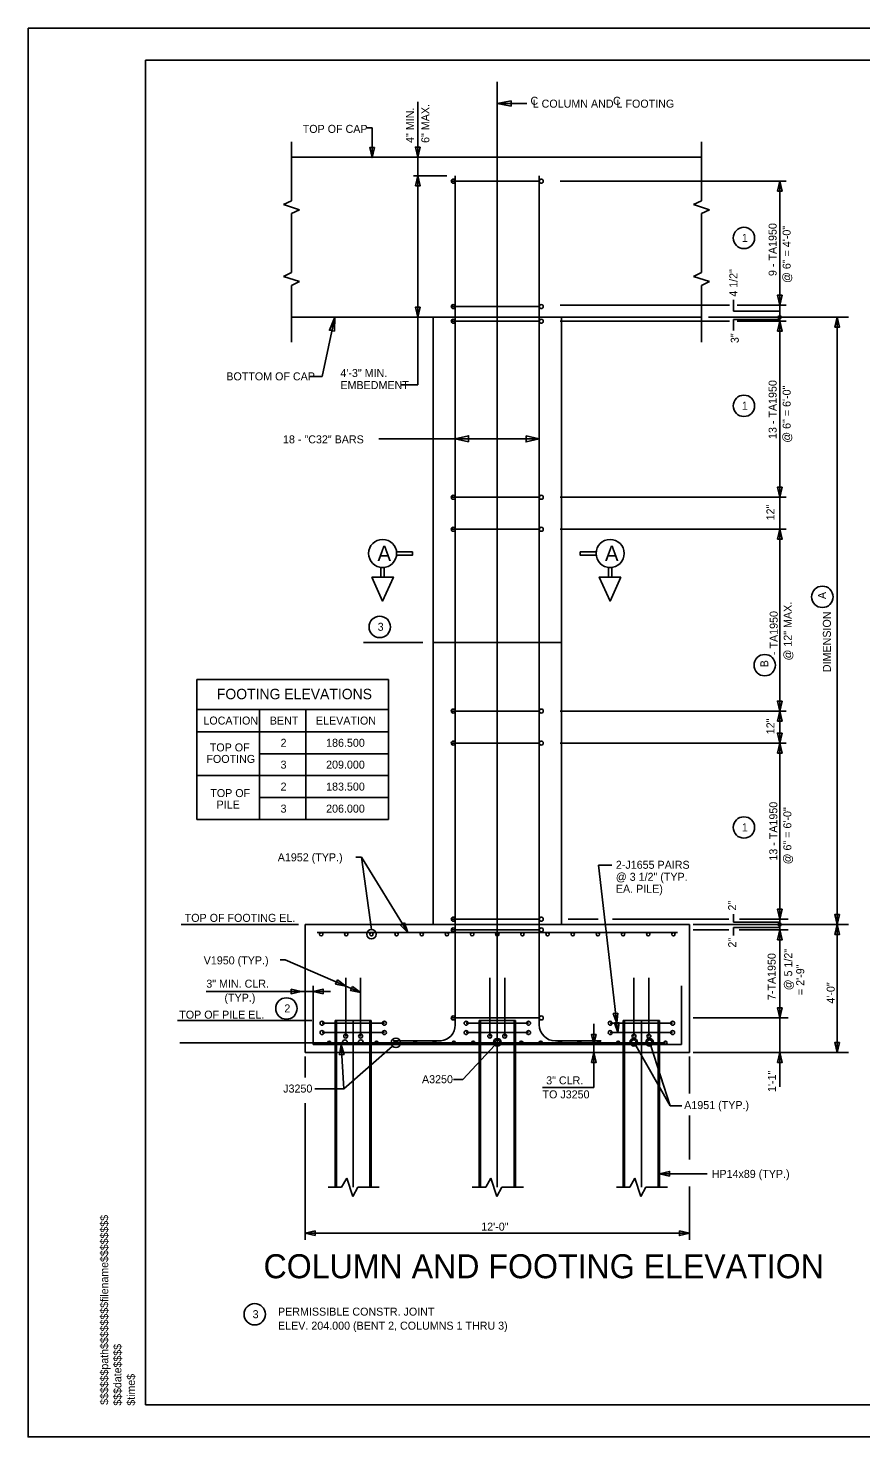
# Model space of a CAD drawing. Extents: x 1970675.2 to 1970711.3, y 796145.2 to 796167.2.
# Drawn here: x 1970675.24 to 1970688.24, y 796145.25 to 796167.25 of the extents above; entities that cross this region are included whole.
import ezdxf

# ---------------------------------------------------------------- set-up
doc = ezdxf.new("R2010")
doc.units = 0
for name, color, linetype in [('BR_AUTO DIMENSION', 7, 'Continuous'), ('BR_BORDER LINES', 7, 'Continuous'), ('BR_CENTER LINES', 7, 'Continuous'), ('BR_CONCRETE', 7, 'Continuous'), ('BR_REBAR', 7, 'Continuous'), ('BR_STRUCTURAL STEEL', 7, 'Continuous'), ('BR_TABLE LINES', 7, 'Continuous'), ('BR_TEXT', 7, 'Continuous'), ('Default', 7, 'Continuous'), ('Level 31', 7, 'Continuous'), ('RD_SHT_ID', 7, 'Continuous')]:
    doc.layers.add(name, color=color, linetype=linetype)

msp = doc.modelspace()

# ---------------------------------------------------------------- linework, layer by layer
at = {"layer": 'BR_AUTO DIMENSION'}
for p, q in [((1970681.318, 796164.939), (1970681.318, 796166.096)), ((1970682.561, 796166.069), (1970683.022, 796166.069)), ((1970681.774, 796164.939), (1970681.254, 796164.939)), ((1970681.318, 796164.939), (1970681.318, 796161.677)), ((1970683.541, 796164.857), (1970687.071, 796164.857)), ((1970686.97, 796164.857), (1970686.97, 796153.247)), ((1970686.247, 796162.829), (1970686.247, 796163.002)), ((1970686.97, 796162.92), (1970686.97, 796163.012)), ((1970683.541, 796162.92), (1970686.186, 796162.92)), ((1970686.247, 796162.829), (1970686.97, 796162.829)), ((1970686.305, 796162.92), (1970687.071, 796162.92)), ((1970679.827, 796161.807), (1970680.025, 796162.732)), ((1970683.541, 796162.67), (1970686.186, 796162.67)), ((1970685.859, 796162.732), (1970688.046, 796162.732)), ((1970686.247, 796162.696), (1970686.97, 796162.696)), ((1970686.247, 796162.696), (1970686.247, 796162.523)), ((1970686.305, 796162.67), (1970687.071, 796162.67)), ((1970686.97, 796162.67), (1970686.97, 796162.543)), ((1970687.866, 796162.732), (1970687.866, 796153.247)), ((1970679.64, 796161.807), (1970679.827, 796161.807)), ((1970681.318, 796161.677), (1970681.058, 796161.677)), ((1970680.712, 796160.832), (1970683.217, 796160.832)), ((1970683.541, 796159.92), (1970687.071, 796159.92)), ((1970683.541, 796159.42), (1970687.071, 796159.42)), ((1970680.47, 796157.65), (1970681.4, 796157.65)), ((1970683.541, 796156.581), (1970687.071, 796156.581)), ((1970683.541, 796156.081), (1970687.071, 796156.081)), ((1970680.352, 796154.299), (1970680.438, 796154.299)), ((1970680.438, 796154.299), (1970680.596, 796153.17)), ((1970680.438, 796154.299), (1970681.164, 796153.122)), ((1970684.14, 796154.176), (1970684.347, 796154.176)), ((1970684.14, 796154.176), (1970684.443, 796151.56)), ((1970683.669, 796153.331), (1970684.134, 796153.331)), ((1970684.357, 796153.331), (1970686.175, 796153.331)), ((1970686.247, 796153.41), (1970686.247, 796153.285)), ((1970686.247, 796153.285), (1970686.97, 796153.285)), ((1970686.34, 796153.331), (1970687.103, 796153.331)), ((1970679.456, 796153.247), (1970677.627, 796153.247)), ((1970685.621, 796153.247), (1970688.046, 796153.247)), ((1970685.621, 796153.164), (1970686.175, 796153.164)), ((1970686.247, 796153.074), (1970686.247, 796153.199)), ((1970686.247, 796153.199), (1970686.97, 796153.199)), ((1970686.335, 796153.164), (1970687.103, 796153.164)), ((1970686.97, 796153.247), (1970686.97, 796150.712)), ((1970687.866, 796153.247), (1970687.866, 796151.247)), ((1970679.25, 796152.695), (1970679.17, 796152.695)), ((1970679.25, 796152.695), (1970680.427, 796152.187)), ((1970679.959, 796152.203), (1970678.013, 796152.203)), ((1970679.666, 796151.747), (1970677.569, 796151.747)), ((1970685.621, 796151.789), (1970687.103, 796151.789)), ((1970686.97, 796151.747), (1970686.97, 796151.631)), ((1970684.066, 796151.695), (1970684.066, 796150.702)), ((1970680.123, 796151.372), (1970680.165, 796150.683)), ((1970680.922, 796151.35), (1970680.165, 796150.683)), ((1970682.024, 796150.825), (1970682.52, 796151.365)), ((1970685.258, 796150.414), (1970684.722, 796151.357)), ((1970685.258, 796150.414), (1970684.957, 796151.352)), ((1970679.561, 796151.187), (1970679.561, 796150.856)), ((1970685.561, 796151.187), (1970685.561, 796150.609)), ((1970685.621, 796151.247), (1970688.046, 796151.247)), ((1970680.165, 796150.683), (1970679.711, 796150.683)), ((1970681.879, 796150.825), (1970682.024, 796150.825)), ((1970683.265, 796150.702), (1970684.066, 796150.702)), ((1970679.561, 796150.458), (1970679.561, 796150.274)), ((1970679.561, 796150.274), (1970679.561, 796148.324)), ((1970685.441, 796150.414), (1970685.258, 796150.414)), ((1970685.561, 796150.263), (1970685.561, 796149.575)), ((1970685.094, 796149.355), (1970685.837, 796149.355)), ((1970679.92, 796149.144), (1970680.13, 796149.144)), ((1970680.209, 796149.288), (1970680.13, 796149.144)), ((1970680.209, 796149.288), (1970680.304, 796149)), ((1970680.382, 796149.144), (1970680.304, 796149)), ((1970680.382, 796149.144), (1970680.718, 796149.144)), ((1970682.17, 796149.144), (1970682.38, 796149.144)), ((1970682.459, 796149.288), (1970682.38, 796149.144)), ((1970682.459, 796149.288), (1970682.554, 796149)), ((1970682.632, 796149.144), (1970682.554, 796149)), ((1970682.632, 796149.144), (1970682.968, 796149.144)), ((1970684.42, 796149.144), (1970684.63, 796149.144)), ((1970684.709, 796149.288), (1970684.63, 796149.144)), ((1970684.709, 796149.288), (1970684.804, 796149)), ((1970684.882, 796149.144), (1970684.804, 796149)), ((1970684.882, 796149.144), (1970685.218, 796149.144)), ((1970685.561, 796149.158), (1970685.561, 796148.324)), ((1970679.561, 796148.426), (1970685.561, 796148.426))]:
    msp.add_line(p, q, dxfattribs=at)
for points in [[(1970682.777, 796166.028), (1970682.561, 796166.069), (1970682.777, 796166.111)], [(1970681.354, 796165.388), (1970681.318, 796165.232), (1970681.282, 796165.388)], [(1970680.641, 796165.381), (1970680.605, 796165.225), (1970680.569, 796165.381)], [(1970681.282, 796164.783), (1970681.318, 796164.939), (1970681.354, 796164.783)], [(1970686.934, 796164.701), (1970686.97, 796164.857), (1970687.006, 796164.701)], [(1970687.006, 796163.076), (1970686.97, 796162.92), (1970686.934, 796163.076)], [(1970681.354, 796162.888), (1970681.318, 796162.732), (1970681.282, 796162.888)], [(1970680.02, 796162.512), (1970680.025, 796162.732), (1970679.939, 796162.529)], [(1970686.934, 796162.514), (1970686.97, 796162.67), (1970687.006, 796162.514)], [(1970687.83, 796162.576), (1970687.866, 796162.732), (1970687.902, 796162.576)], [(1970682.112, 796160.784), (1970681.904, 796160.832), (1970682.112, 796160.88)], [(1970683.009, 796160.88), (1970683.217, 796160.832), (1970683.009, 796160.784)], [(1970687.006, 796160.076), (1970686.97, 796159.92), (1970686.934, 796160.076)], [(1970686.934, 796159.264), (1970686.97, 796159.42), (1970687.006, 796159.264)], [(1970687.006, 796156.737), (1970686.97, 796156.581), (1970686.934, 796156.737)], [(1970686.934, 796156.425), (1970686.97, 796156.581), (1970687.006, 796156.425)], [(1970687.006, 796156.237), (1970686.97, 796156.081), (1970686.934, 796156.237)], [(1970686.934, 796155.925), (1970686.97, 796156.081), (1970687.006, 796155.925)], [(1970687.006, 796153.487), (1970686.97, 796153.331), (1970686.934, 796153.487)], [(1970687.902, 796153.403), (1970687.866, 796153.247), (1970687.83, 796153.403)], [(1970681.113, 796153.274), (1970681.164, 796153.122), (1970681.051, 796153.236)], [(1970686.934, 796153.008), (1970686.97, 796153.164), (1970687.006, 796153.008)], [(1970687.83, 796153.091), (1970687.866, 796153.247), (1970687.902, 796153.091)], [(1970679.342, 796152.239), (1970679.498, 796152.203), (1970679.342, 796152.167)], [(1970679.842, 796152.167), (1970679.686, 796152.203), (1970679.842, 796152.239)], [(1970680.065, 796152.382), (1970680.194, 796152.287), (1970680.036, 796152.316)], [(1970680.298, 796152.282), (1970680.427, 796152.187), (1970680.27, 796152.216)], [(1970684.444, 796151.865), (1970684.426, 796151.706), (1970684.372, 796151.856)], [(1970687.006, 796151.945), (1970686.97, 796151.789), (1970686.934, 796151.945)], [(1970684.102, 796151.528), (1970684.066, 796151.372), (1970684.03, 796151.528)], [(1970684.461, 796151.719), (1970684.443, 796151.56), (1970684.389, 796151.71)], [(1970680.096, 796151.214), (1970680.123, 796151.372), (1970680.168, 796151.219)], [(1970687.902, 796151.403), (1970687.866, 796151.247), (1970687.83, 796151.403)], [(1970684.03, 796151.091), (1970684.066, 796151.247), (1970684.102, 796151.091)], [(1970686.934, 796151.091), (1970686.97, 796151.247), (1970687.006, 796151.091)], [(1970685.25, 796149.319), (1970685.094, 796149.355), (1970685.25, 796149.391)], [(1970679.717, 796148.39), (1970679.561, 796148.426), (1970679.717, 796148.462)], [(1970685.405, 796148.462), (1970685.561, 796148.426), (1970685.405, 796148.39)]]:
    msp.add_lwpolyline(points, close=True, dxfattribs=at)
msp.add_lwpolyline([(1970680.605, 796165.225), (1970680.605, 796165.689), (1970680.527, 796165.689)], dxfattribs=at)
for centre, radius in [((1970686.412, 796163.97), 0.167), ((1970686.97, 796162.732), 0.0235), ((1970686.412, 796161.348), 0.167), ((1970687.636, 796158.365), 0.167), ((1970680.726, 796157.896), 0.167), ((1970686.736, 796157.298), 0.167), ((1970686.412, 796154.763), 0.167), ((1970686.97, 796153.247), 0.0235), ((1970679.269, 796151.936), 0.167), ((1970678.774, 796147.16), 0.167)]:
    msp.add_circle(centre, radius, dxfattribs=at)
at = {"layer": 'BR_BORDER LINES'}
for p, q in [((1970710.736, 796166.746), (1970677.07, 796166.746)), ((1970677.07, 796145.746), (1970677.07, 796166.746)), ((1970677.07, 796145.746), (1970710.736, 796145.746))]:
    msp.add_line(p, q, dxfattribs=at)
at = {"layer": 'BR_CENTER LINES'}
for p, q in [((1970682.561, 796151.747), (1970682.561, 796166.409)), ((1970680.311, 796151.747), (1970680.311, 796149.144)), ((1970682.561, 796151.747), (1970682.561, 796149.144)), ((1970684.811, 796151.747), (1970684.811, 796149.144))]:
    msp.add_line(p, q, dxfattribs=at)
at = {"layer": 'BR_CONCRETE'}
for p, q in [((1970679.348, 796165.232), (1970685.748, 796165.232)), ((1970679.348, 796162.732), (1970685.748, 796162.732)), ((1970681.561, 796162.732), (1970681.561, 796153.247)), ((1970683.561, 796162.732), (1970683.561, 796153.247)), ((1970681.561, 796157.65), (1970683.561, 796157.65)), ((1970679.561, 796153.247), (1970685.561, 796153.247)), ((1970679.561, 796153.247), (1970679.561, 796151.247)), ((1970685.561, 796153.247), (1970685.561, 796151.247)), ((1970679.561, 796151.247), (1970685.561, 796151.247))]:
    msp.add_line(p, q, dxfattribs=at)
at = {"layer": 'BR_REBAR'}
for p, q in [((1970681.842, 796164.857), (1970683.217, 796164.857)), ((1970681.904, 796164.939), (1970681.904, 796154.623)), ((1970683.217, 796164.939), (1970683.217, 796154.623)), ((1970681.904, 796164.325), (1970681.904, 796153.247)), ((1970683.217, 796164.325), (1970683.217, 796151.679)), ((1970681.842, 796162.899), (1970683.217, 796162.899)), ((1970681.842, 796162.67), (1970683.217, 796162.67)), ((1970681.842, 796159.92), (1970683.217, 796159.92)), ((1970681.842, 796159.42), (1970683.217, 796159.42)), ((1970681.842, 796156.581), (1970683.217, 796156.581)), ((1970681.842, 796156.081), (1970683.217, 796156.081)), ((1970681.904, 796154.623), (1970681.904, 796151.678)), ((1970681.842, 796153.331), (1970683.217, 796153.331)), ((1970679.748, 796153.122), (1970685.373, 796153.122)), ((1970681.842, 796153.164), (1970683.217, 796153.164)), ((1970680.194, 796151.497), (1970680.194, 796152.417)), ((1970680.427, 796151.497), (1970680.427, 796152.417)), ((1970682.444, 796151.497), (1970682.444, 796152.417)), ((1970682.677, 796151.497), (1970682.677, 796152.417)), ((1970684.694, 796151.497), (1970684.694, 796152.417)), ((1970684.927, 796151.497), (1970684.927, 796152.417)), ((1970679.686, 796151.372), (1970679.686, 796152.289)), ((1970685.436, 796151.372), (1970685.436, 796152.289)), ((1970681.842, 796151.788), (1970683.217, 796151.788)), ((1970680.798, 796151.706), (1970679.824, 796151.706)), ((1970680.798, 796151.56), (1970679.824, 796151.56)), ((1970682.074, 796151.706), (1970683.048, 796151.706)), ((1970682.074, 796151.56), (1970683.048, 796151.56)), ((1970684.324, 796151.706), (1970685.298, 796151.706)), ((1970684.324, 796151.56), (1970685.298, 796151.56)), ((1970679.686, 796151.372), (1970685.436, 796151.372)), ((1970680.936, 796151.429), (1970681.682, 796151.429)), ((1970683.467, 796151.429), (1970684.185, 796151.429))]:
    msp.add_line(p, q, dxfattribs=at)
for centre, radius in [((1970681.873, 796164.857), 0.0313), ((1970683.248, 796164.857), 0.0313), ((1970681.873, 796162.899), 0.0313), ((1970683.248, 796162.899), 0.0313), ((1970681.873, 796162.67), 0.0313), ((1970683.248, 796162.67), 0.0313), ((1970681.873, 796159.92), 0.0313), ((1970683.248, 796159.92), 0.0313), ((1970681.873, 796159.42), 0.0313), ((1970683.248, 796159.42), 0.0313), ((1970681.873, 796156.581), 0.0313), ((1970683.248, 796156.581), 0.0313), ((1970681.873, 796156.081), 0.0313), ((1970683.248, 796156.081), 0.0313), ((1970681.873, 796153.331), 0.0313), ((1970683.248, 796153.331), 0.0313), ((1970679.811, 796153.096), 0.0265), ((1970680.203, 796153.096), 0.0265), ((1970680.596, 796153.096), 0.0265), ((1970680.989, 796153.096), 0.0265), ((1970681.382, 796153.096), 0.0265), ((1970681.775, 796153.096), 0.0265), ((1970681.873, 796153.164), 0.0313), ((1970682.168, 796153.096), 0.0265), ((1970682.561, 796153.096), 0.0265), ((1970682.953, 796153.096), 0.0265), ((1970683.248, 796153.164), 0.0313), ((1970683.346, 796153.096), 0.0265), ((1970683.739, 796153.096), 0.0265), ((1970684.132, 796153.096), 0.0265), ((1970684.525, 796153.096), 0.0265), ((1970684.918, 796153.096), 0.0265), ((1970685.311, 796153.096), 0.0265), ((1970681.873, 796151.788), 0.0313), ((1970683.248, 796151.788), 0.0313), ((1970679.824, 796151.706), 0.0313), ((1970679.824, 796151.56), 0.0313), ((1970680.194, 796151.504), 0.0313), ((1970680.427, 796151.504), 0.0313), ((1970680.798, 796151.706), 0.0313), ((1970680.798, 796151.56), 0.0313), ((1970682.074, 796151.706), 0.0313), ((1970682.074, 796151.56), 0.0313), ((1970682.444, 796151.504), 0.0313), ((1970682.677, 796151.504), 0.0313), ((1970683.048, 796151.706), 0.0313), ((1970683.048, 796151.56), 0.0313), ((1970684.324, 796151.706), 0.0313), ((1970684.324, 796151.56), 0.0313), ((1970684.694, 796151.504), 0.0313), ((1970684.927, 796151.504), 0.0313), ((1970685.298, 796151.706), 0.0313), ((1970685.298, 796151.56), 0.0313), ((1970679.936, 796151.4), 0.0265), ((1970680.182, 796151.409), 0.0366), ((1970680.429, 796151.409), 0.0366), ((1970680.675, 796151.4), 0.0265), ((1970680.977, 796151.4), 0.0265), ((1970681.279, 796151.4), 0.0265), ((1970681.581, 796151.4), 0.0265), ((1970681.883, 796151.4), 0.0265), ((1970682.186, 796151.4), 0.0265), ((1970682.561, 796151.409), 0.0366), ((1970682.936, 796151.4), 0.0265), ((1970683.238, 796151.4), 0.0265), ((1970683.54, 796151.4), 0.0265), ((1970683.842, 796151.4), 0.0265), ((1970684.144, 796151.4), 0.0265), ((1970684.446, 796151.4), 0.0265), ((1970684.692, 796151.409), 0.0366), ((1970684.939, 796151.409), 0.0366), ((1970685.186, 796151.4), 0.0265)]:
    msp.add_circle(centre, radius, dxfattribs=at)
for centre, start, end in [((1970681.654, 796151.678), 276.3821, 360), ((1970683.467, 796151.679), 180, 270)]:
    msp.add_arc(centre, 0.25, start, end, dxfattribs=at)
at = {"layer": 'BR_STRUCTURAL STEEL'}
for p, q in [((1970680.027, 796151.247), (1970680.027, 796151.747)), ((1970680.027, 796151.747), (1970680.594, 796151.747)), ((1970680.048, 796151.247), (1970680.048, 796151.747)), ((1970680.573, 796151.247), (1970680.573, 796151.747)), ((1970680.594, 796151.247), (1970680.594, 796151.747)), ((1970682.277, 796151.747), (1970682.844, 796151.747)), ((1970682.277, 796151.247), (1970682.277, 796151.747)), ((1970682.298, 796151.247), (1970682.298, 796151.747)), ((1970682.823, 796151.247), (1970682.823, 796151.747)), ((1970682.844, 796151.247), (1970682.844, 796151.747)), ((1970684.527, 796151.247), (1970684.527, 796151.747)), ((1970684.527, 796151.747), (1970685.094, 796151.747)), ((1970684.548, 796151.247), (1970684.548, 796151.747)), ((1970685.073, 796151.247), (1970685.073, 796151.747)), ((1970685.094, 796151.247), (1970685.094, 796151.747)), ((1970680.027, 796149.144), (1970680.027, 796151.247)), ((1970680.048, 796149.144), (1970680.048, 796151.247)), ((1970680.573, 796149.144), (1970680.573, 796151.247)), ((1970680.594, 796149.144), (1970680.594, 796151.247)), ((1970682.277, 796149.144), (1970682.277, 796151.247)), ((1970682.298, 796149.144), (1970682.298, 796151.247)), ((1970682.823, 796149.144), (1970682.823, 796151.247)), ((1970682.844, 796149.144), (1970682.844, 796151.247)), ((1970684.527, 796149.144), (1970684.527, 796151.247)), ((1970684.548, 796149.144), (1970684.548, 796151.247)), ((1970685.073, 796149.144), (1970685.073, 796151.247)), ((1970685.094, 796149.144), (1970685.094, 796151.247))]:
    msp.add_line(p, q, dxfattribs=at)
at = {"layer": 'BR_TABLE LINES'}
for p, q in [((1970677.869, 796157.072), (1970680.862, 796157.072)), ((1970677.869, 796154.886), (1970677.869, 796157.072)), ((1970680.862, 796154.886), (1970680.862, 796157.072)), ((1970677.869, 796156.607), (1970680.862, 796156.607)), ((1970678.847, 796154.886), (1970678.847, 796156.607)), ((1970679.573, 796154.886), (1970679.573, 796156.607)), ((1970677.869, 796156.257), (1970680.862, 796156.257)), ((1970678.847, 796155.915), (1970680.862, 796155.915)), ((1970677.869, 796155.573), (1970680.862, 796155.573)), ((1970678.847, 796155.573), (1970680.862, 796155.573)), ((1970678.847, 796155.229), (1970680.862, 796155.229)), ((1970677.869, 796154.886), (1970680.862, 796154.886))]:
    msp.add_line(p, q, dxfattribs=at)
at = {"layer": 'BR_TEXT'}
for points in [[(1970681.239, 796159.068), (1970681.239, 796159.018), (1970680.989, 796159.018), (1970680.989, 796159.068)], [(1970683.853, 796159.068), (1970683.853, 796159.018), (1970684.103, 796159.018), (1970684.103, 796159.068)], [(1970680.795, 796158.824), (1970680.795, 796158.674), (1970680.745, 796158.674), (1970680.745, 796158.824)], [(1970684.297, 796158.824), (1970684.297, 796158.674), (1970684.347, 796158.674), (1970684.347, 796158.824)], [(1970680.601, 796158.674), (1970680.77, 796158.299), (1970680.939, 796158.674)], [(1970684.491, 796158.674), (1970684.322, 796158.299), (1970684.153, 796158.674)]]:
    msp.add_lwpolyline(points, close=True, dxfattribs=at)
for centre, radius in [((1970680.77, 796159.043), 0.219), ((1970684.322, 796159.043), 0.219), ((1970680.596, 796153.096), 0.0744), ((1970680.977, 796151.4), 0.0744), ((1970682.561, 796151.409), 0.0595), ((1970684.692, 796151.409), 0.0595), ((1970684.939, 796151.409), 0.0595)]:
    msp.add_circle(centre, radius, dxfattribs=at)
at = {"layer": 'Default'}
for p, q in [((1970679.348, 796165.47), (1970679.348, 796164.551)), ((1970685.748, 796165.47), (1970685.748, 796164.551)), ((1970679.223, 796164.49), (1970679.348, 796164.551)), ((1970685.623, 796164.49), (1970685.748, 796164.551)), ((1970679.473, 796164.411), (1970679.223, 796164.49)), ((1970679.348, 796164.35), (1970679.473, 796164.411)), ((1970679.348, 796163.431), (1970679.348, 796164.35)), ((1970685.873, 796164.411), (1970685.623, 796164.49)), ((1970685.748, 796164.35), (1970685.873, 796164.411)), ((1970685.748, 796163.431), (1970685.748, 796164.35)), ((1970679.223, 796163.37), (1970679.348, 796163.431)), ((1970685.623, 796163.37), (1970685.748, 796163.431)), ((1970679.473, 796163.292), (1970679.223, 796163.37)), ((1970679.348, 796163.23), (1970679.473, 796163.292)), ((1970679.348, 796162.344), (1970679.348, 796163.23)), ((1970679.348, 796163.17), (1970679.348, 796163.23)), ((1970685.873, 796163.292), (1970685.623, 796163.37)), ((1970685.748, 796163.23), (1970685.873, 796163.292)), ((1970685.748, 796162.344), (1970685.748, 796163.23)), ((1970685.748, 796163.17), (1970685.748, 796163.23))]:
    msp.add_line(p, q, dxfattribs=at)
at = {"layer": 'Level 31'}
for p, q in [((1970711.236, 796167.246), (1970675.236, 796167.246)), ((1970685.186, 796151.4), (1970677.604, 796151.4))]:
    msp.add_line(p, q, dxfattribs=at)
msp.add_lwpolyline([(1970675.236, 796167.246), (1970675.236, 796145.246), (1970711.236, 796145.246), (1970711.236, 796167.246)], dxfattribs=at)

# ---------------------------------------------------------------- texts
at = {"layer": 'BR_TEXT'}
for s, p in [('6" MAX.', (1970681.5, 796165.454)), ('4" MIN.', (1970681.259, 796165.454)), ('9 - TA1950', (1970686.922, 796163.375)), ('@ 6" = 4\'-0"', (1970687.141, 796163.267)), ('4 1/2"', (1970686.31, 796163.052)), ('3"', (1970686.331, 796162.328)), ('13 - TA1950', (1970686.922, 796160.83)), ('@ 6" = 6\'-0"', (1970687.141, 796160.772)), ('12"', (1970686.888, 796159.559)), ('A', (1970687.693, 796158.33)), ('  - TA1950', (1970686.939, 796157.363)), ('@ 12" MAX.', (1970687.158, 796157.371)), ('DIMENSION', (1970687.769, 796157.189)), ('B', (1970686.793, 796157.265)), ('12"', (1970686.888, 796156.219)), ('13 - TA1950', (1970686.933, 796154.245)), ('@ 6" = 6\'-0"', (1970687.152, 796154.187)), ('2"', (1970686.29, 796153.466)), ('2"', (1970686.291, 796152.888)), ('@ 5 1/2"', (1970687.165, 796152.22)), ('7-TA1950', (1970686.907, 796152.067)), ('= 2\'-9"', (1970687.353, 796152.146)), ('4\'-0"', (1970687.829, 796152.012)), ('1\'-1"', (1970686.911, 796150.632))]:
    msp.add_text(s, height=0.125, rotation=90, dxfattribs=at).set_placement(p)
for s, height, p in [('C', 0.125, (1970683.079, 796166.05)), ('L COLUMN AND L FOOTING', 0.125, (1970683.113, 796166.005)), ('C', 0.125, (1970684.368, 796166.05)), ('TOP OF CAP', 0.125, (1970679.523, 796165.611)), ('1', 0.125, (1970686.379, 796163.909)), ('BOTTOM OF CAP', 0.125, (1970678.33, 796161.746)), ('4\'-3" MIN.', 0.125, (1970680.111, 796161.798)), ('EMBEDMENT', 0.125, (1970680.111, 796161.61)), ('1', 0.125, (1970686.379, 796161.287)), ('18 - "C32" BARS', 0.125, (1970679.215, 796160.762)), ('A', 0.24, (1970680.689, 796158.923)), ('A', 0.24, (1970684.241, 796158.923)), ('3', 0.125, (1970680.693, 796157.835)), ('FOOTING ELEVATIONS', 0.16305, (1970678.182, 796156.766)), ('LOCATION', 0.125, (1970677.972, 796156.37)), ('BENT', 0.125, (1970679.009, 796156.37)), ('ELEVATION', 0.125, (1970679.729, 796156.37)), ('2', 0.125, (1970679.177, 796156.023)), ('186.500', 0.125, (1970679.888, 796156.023)), ('TOP OF ', 0.125, (1970678.072, 796155.951)), ('FOOTING', 0.125, (1970678.019, 796155.771)), ('3', 0.125, (1970679.177, 796155.682)), ('209.000', 0.125, (1970679.888, 796155.682)), ('TOP OF', 0.125, (1970678.08, 796155.238)), ('2', 0.125, (1970679.177, 796155.339)), ('183.500', 0.125, (1970679.888, 796155.339)), ('PILE', 0.125, (1970678.178, 796155.058)), ('3', 0.125, (1970679.177, 796154.995)), ('206.000', 0.125, (1970679.888, 796154.995)), ('1', 0.125, (1970686.379, 796154.702)), ('A1952 (TYP.)', 0.125, (1970679.133, 796154.234)), ('2-J1655 PAIRS', 0.125, (1970684.412, 796154.118)), ('@ 3 1/2" (TYP.', 0.125, (1970684.412, 796153.93)), ('EA. PILE)', 0.125, (1970684.412, 796153.743)), ('TOP OF FOOTING EL.', 0.125, (1970677.68, 796153.289)), ('V1950 (TYP.)', 0.125, (1970677.977, 796152.625)), (' 3" MIN. CLR.', 0.125, (1970677.971, 796152.261)), ('(TYP.)', 0.125, (1970678.301, 796152.042)), ('2', 0.125, (1970679.236, 796151.875)), ('TOP OF PILE EL.', 0.125, (1970677.595, 796151.777)), ('A3250', 0.125, (1970681.385, 796150.769)), ('3" CLR.', 0.125, (1970683.324, 796150.751)), ('J3250', 0.125, (1970679.218, 796150.623)), ('TO J3250', 0.125, (1970683.267, 796150.532)), ('A1951 (TYP.)', 0.125, (1970685.479, 796150.365)), ('HP14x89 (TYP.)', 0.125, (1970685.908, 796149.29)), ('12\'-0"', 0.125, (1970682.31, 796148.466)), ('COLUMN AND FOOTING ELEVATION', 0.375, (1970678.911, 796147.723)), ('3', 0.125, (1970678.741, 796147.099)), ('PERMISSIBLE CONSTR. JOINT ', 0.125, (1970679.137, 796147.139)), ('ELEV. 204.000 (BENT 2, COLUMNS 1 THRU 3)', 0.125, (1970679.137, 796146.92))]:
    msp.add_text(s, height=height, dxfattribs=at).set_placement(p)
at = {"layer": 'RD_SHT_ID'}
for s, height, p in [('$$$$$$path$$$$$$$$filename$$$$$$$$', 0.12347, (1970676.486, 796145.746)), ('$$$date$$$$', 0.12347, (1970676.692, 796145.733)), ('$time$', 0.1235, (1970676.903, 796145.733))]:
    msp.add_text(s, height=height, rotation=90, dxfattribs=at).set_placement(p)

doc.saveas('drawing.dxf')
